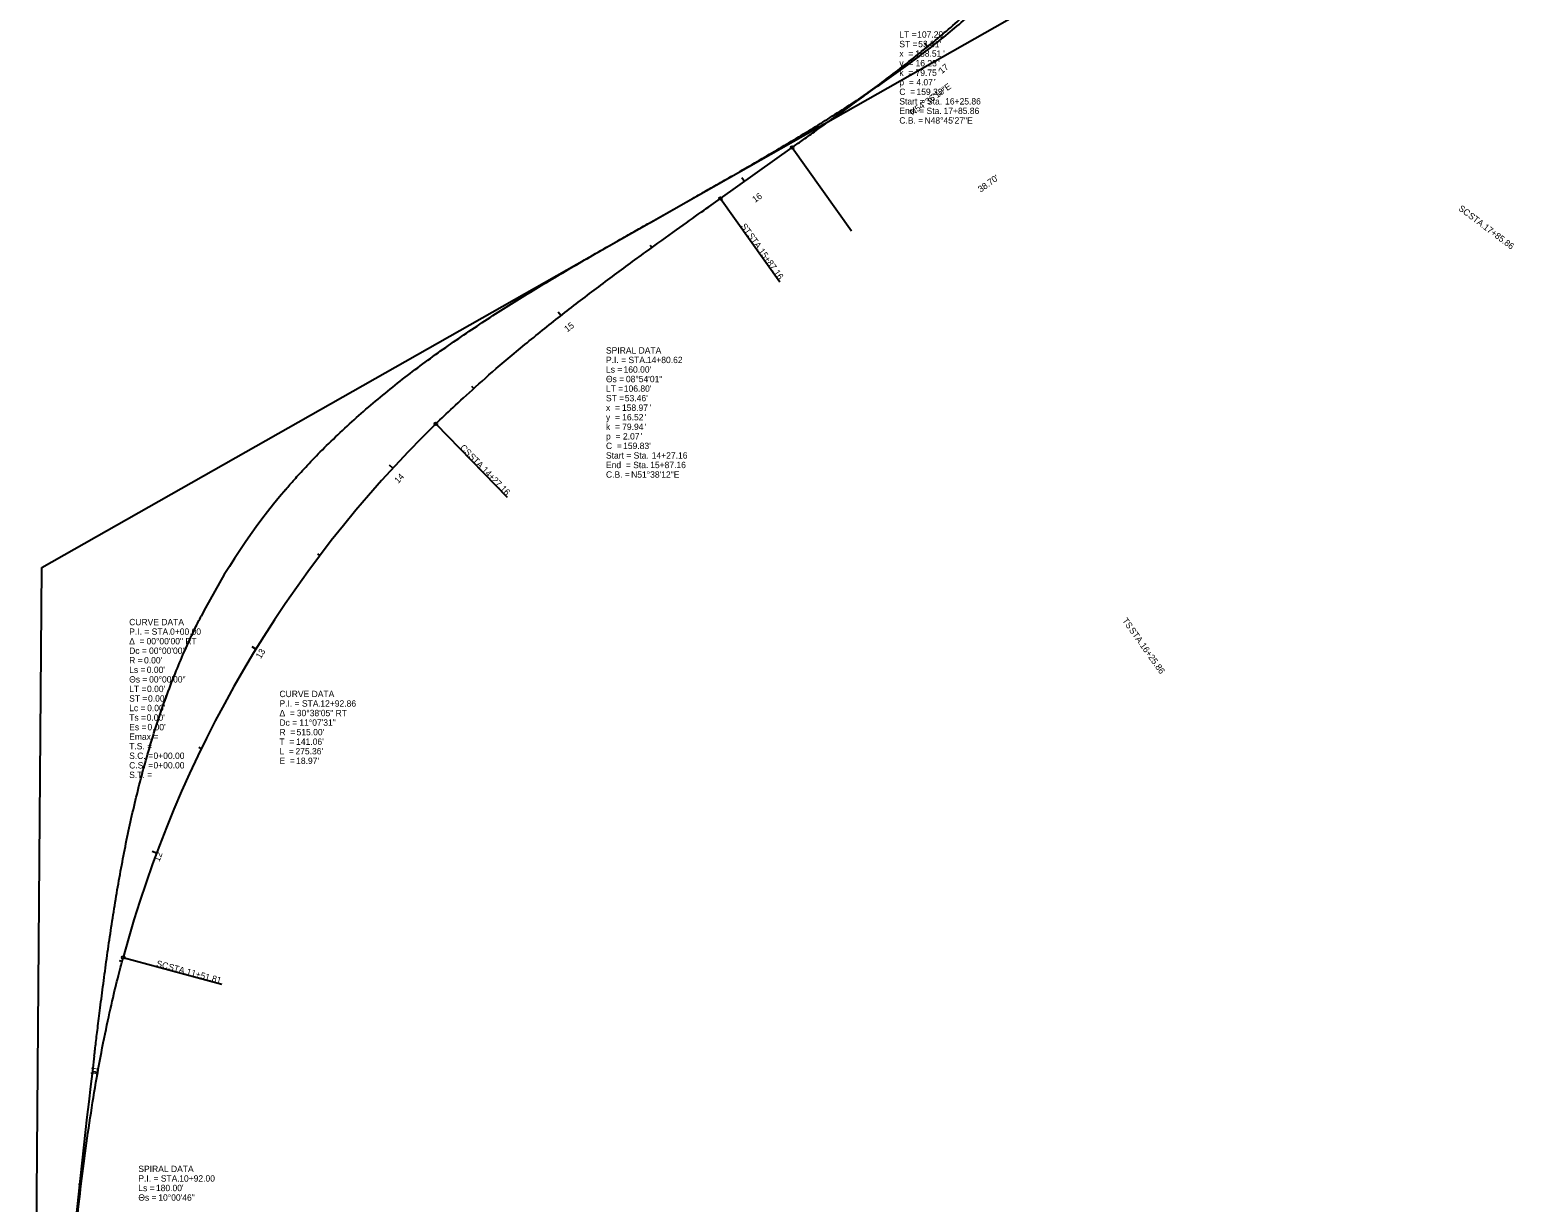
# Model space of a CAD drawing. Extents: x 1504629 to 1506299, y 325931 to 328016.
# Drawn here: x 1504639 to 1505293, y 326974 to 327489 of the extents above; entities that cross this region are included whole.
import ezdxf

# ---------------------------------------------------------------- set-up
doc = ezdxf.new("R2010")
doc.units = 0
for name, color, linetype in [('DV_X_Property_Line', 7, 'Continuous'), ('GE_X_Alignment', 7, 'Continuous'), ('GE_X_Alignment_100_Bearings', 7, 'Continuous'), ('GE_X_Alignment_100_Cardinal_Points', 7, 'Continuous'), ('GE_X_Alignment_100_Curve_Data', 7, 'Continuous'), ('GE_X_Alignment_100_Distances', 7, 'Continuous'), ('GE_X_Alignment_100_Stations', 7, 'Continuous'), ('SC_Scratch7', 7, 'Continuous'), ('SC_Scratch8', 7, 'Continuous')]:
    doc.layers.add(name, color=color, linetype=linetype)

msp = doc.modelspace()

# ---------------------------------------------------------------- linework, layer by layer
at = {"layer": 'DV_X_Property_Line'}
msp.add_line((1504943.35, 327415.15), (1504974.89, 327437.57), dxfattribs=at)
at = {"layer": 'GE_X_Alignment'}
msp.add_line((1504943.35, 327415.15), (1504974.89, 327437.57), dxfattribs=at)
msp.add_arc((1505177.7, 326947.36), 515, 134.2975, 164.93216, dxfattribs=at)
msp.add_arc((1505177.7, 326947.36), 515, 134.2975, 164.93216, dxfattribs=at)
for points in [[(1504974.89, 327437.57), (1504976.25, 327438.53), (1504978.97, 327440.47), (1504984.4, 327444.33), (1504991.18, 327449.17), (1504999.29, 327455.02), (1505007.36, 327460.93), (1505015.37, 327466.92), (1505023.31, 327473), (1505031.16, 327479.2), (1505038.91, 327485.52), (1505046.53, 327491.99), (1505054.01, 327498.63), (1505061.33, 327505.44), (1505068.47, 327512.44), (1505075.41, 327519.65), (1505082.12, 327527.07), (1505087.5, 327533.43), (1505091.66, 327538.64), (1505093.7, 327541.28), (1505094.7, 327542.61)], [(1504818.03, 327315.96), (1504820.42, 327318.28), (1504825.23, 327322.89), (1504835.03, 327331.94), (1504847.57, 327342.92), (1504862.98, 327355.67), (1504878.71, 327368.03), (1504894.67, 327380.08), (1504910.8, 327391.91), (1504924.34, 327401.63), (1504935.2, 327409.36), (1504940.63, 327413.22), (1504943.35, 327415.15)], [(1504818.03, 327315.96), (1504820.42, 327318.28), (1504825.23, 327322.89), (1504835.03, 327331.94), (1504847.57, 327342.92), (1504862.98, 327355.67), (1504878.71, 327368.03), (1504894.67, 327380.08), (1504910.8, 327391.91), (1504924.34, 327401.63), (1504935.2, 327409.36), (1504940.63, 327413.22), (1504943.35, 327415.15)], [(1504654.17, 326903.41), (1504654.43, 326906.4), (1504654.96, 326912.37), (1504656.03, 326924.33), (1504657.41, 326939.26), (1504659.18, 326957.18), (1504661.14, 326975.07), (1504663.35, 326992.93), (1504665.88, 327010.76), (1504668.77, 327028.52), (1504672.1, 327046.21), (1504675.29, 327060.87), (1504678.11, 327072.54), (1504679.62, 327078.34), (1504680.4, 327081.24)], [(1504654.17, 326903.41), (1504654.43, 326906.4), (1504654.96, 326912.37), (1504656.03, 326924.33), (1504657.41, 326939.26), (1504659.18, 326957.18), (1504661.14, 326975.07), (1504663.35, 326992.93), (1504665.88, 327010.76), (1504668.77, 327028.52), (1504672.1, 327046.21), (1504675.29, 327060.87), (1504678.11, 327072.54), (1504679.62, 327078.34), (1504680.4, 327081.24)]]:
    msp.add_open_spline(points, degree=3, dxfattribs=at)
at = {"layer": 'GE_X_Alignment_100_Cardinal_Points'}
for p, q in [((1504974.89, 327437.57), (1505000.96, 327400.89)), ((1504943.35, 327415.15), (1504969.42, 327378.47)), ((1504818.03, 327315.96), (1504849.46, 327283.75)), ((1504680.4, 327081.24), (1504723.86, 327069.54))]:
    msp.add_line(p, q, dxfattribs=at)
for centre in [(1504974.89, 327437.57), (1504943.35, 327415.15), (1504818.03, 327315.96), (1504680.4, 327081.24)]:
    msp.add_circle(centre, 0.6, dxfattribs=at)
at = {"layer": 'GE_X_Alignment_100_Stations'}
for p, q in [((1505034.36, 327481.82), (1505033.1, 327483.37)), ((1504994.54, 327451.6), (1504993.84, 327452.57)), ((1504953.81, 327422.59), (1504952.65, 327424.22)), ((1504913.11, 327393.54), (1504912.41, 327394.51)), ((1504873.09, 327363.58), (1504871.86, 327365.16)), ((1504834.71, 327331.55), (1504833.9, 327332.45)), ((1504799.1, 327296.48), (1504797.63, 327297.84)), ((1504767.04, 327258.14), (1504766.08, 327258.86)), ((1504738.85, 327216.87), (1504737.14, 327217.91)), ((1504714.79, 327173.06), (1504713.71, 327173.58)), ((1504695.09, 327127.12), (1504693.22, 327127.82)), ((1504679.94, 327079.49), (1504678.78, 327079.8)), ((1504669.23, 327030.67), (1504667.26, 327031.02)), ((1504661.92, 326981.21), (1504660.72, 326981.36))]:
    msp.add_line(p, q, dxfattribs=at)
at = {"layer": 'SC_Scratch7'}
for p, q in [((1504644.71, 327252.82), (1505148.27, 327538.35)), ((1504639.3, 326603.71), (1504644.71, 327252.82))]:
    msp.add_line(p, q, dxfattribs=at)
at = {"layer": 'SC_Scratch8'}
msp.add_line((1504912.45, 327404.63), (1504931.21, 327415.27), dxfattribs=at)
for centre, radius, start, end in [((1504969.97, 327101.26), 286.48, 139.55359, 152.98901), ((1508458.87, 326571.85), 3819.7, 172.98893, 179.52215)]:
    msp.add_arc(centre, radius, start, end, dxfattribs=at)
for points in [[(1504931.21, 327415.27), (1504932.66, 327416.09), (1504935.56, 327417.74), (1504941.36, 327421.03), (1504948.6, 327425.15), (1504957.27, 327430.13), (1504965.91, 327435.17), (1504974.51, 327440.26), (1504983.07, 327445.44), (1504991.56, 327450.72), (1504999.98, 327456.11), (1505008.32, 327461.63), (1505016.56, 327467.3), (1505024.7, 327473.12), (1505032.71, 327479.11), (1505040.57, 327485.28), (1505048.29, 327491.64), (1505055.83, 327498.21), (1505063.18, 327505), (1505070.31, 327512), (1505077.22, 327519.24), (1505082.76, 327525.46), (1505087.06, 327530.56), (1505089.16, 327533.15), (1505090.2, 327534.45)], [(1504751.96, 327287.11), (1504753.16, 327288.52), (1504755.59, 327291.32), (1504760.55, 327296.81), (1504766.94, 327303.51), (1504774.89, 327311.28), (1504783.08, 327318.79), (1504791.49, 327326.05), (1504800.11, 327333.07), (1504808.9, 327339.87), (1504817.85, 327346.46), (1504826.94, 327352.85), (1504836.15, 327359.06), (1504845.47, 327365.11), (1504854.88, 327371.02), (1504864.36, 327376.81), (1504873.91, 327382.5), (1504883.5, 327388.11), (1504893.13, 327393.65), (1504901.17, 327398.23), (1504907.62, 327401.89), (1504910.84, 327403.72), (1504912.45, 327404.63)], [(1504667.73, 327038.09), (1504667.95, 327039.92), (1504668.41, 327043.6), (1504669.31, 327050.95), (1504670.46, 327060.14), (1504671.89, 327071.16), (1504673.39, 327082.17), (1504674.98, 327093.16), (1504676.7, 327104.14), (1504678.55, 327115.1), (1504680.57, 327126.03), (1504682.77, 327136.92), (1504685.19, 327147.76), (1504687.84, 327158.55), (1504690.75, 327169.28), (1504693.93, 327179.92), (1504697.41, 327190.48), (1504701.21, 327200.92), (1504705.34, 327211.24), (1504709.07, 327219.71), (1504712.25, 327226.4), (1504713.9, 327229.72), (1504714.74, 327231.37)]]:
    msp.add_open_spline(points, degree=3, dxfattribs=at)

# ---------------------------------------------------------------- texts
at = {"layer": 'GE_X_Alignment_100_Bearings'}
msp.add_text('N54°36\'10"E', height=2.8, rotation=35.39718, dxfattribs=at).set_placement((1505027.8, 327451.48))
at = {"layer": 'GE_X_Alignment_100_Cardinal_Points'}
for s, rotation, p in [('SC', 322.94701, (1505267.76, 327410.24)), ('ST', 305.39718, (1504952.09, 327402.92)), (' STA. ', 322.94701, (1505271.24, 327407.61)), ('17+85.86', 322.94701, (1505278.68, 327401.99)), (' STA. ', 305.39718, (1504954.47, 327399.57)), ('15+87.16', 305.39718, (1504959.87, 327391.97)), ('CS', 314.2975, (1504828.47, 327305.31)), (' STA. ', 314.2975, (1504831.52, 327302.19)), ('14+27.16', 314.2975, (1504838.03, 327295.52)), ('TS', 305.39718, (1505119.93, 327229.44)), (' STA. ', 305.39718, (1505122.32, 327226.09)), ('16+25.86', 305.39718, (1505127.72, 327218.49)), ('SC', 344.93216, (1504694.85, 327077.39)), (' STA. ', 344.93216, (1504699.05, 327076.26)), ('11+51.81', 344.93216, (1504708.06, 327073.83))]:
    msp.add_text(s, height=2.8, rotation=rotation, dxfattribs=at).set_placement(p)
at = {"layer": 'GE_X_Alignment_100_Curve_Data'}
for s, p in [('LT = ', (1505022, 327485.86)), ("107.20'", (1505029.85, 327485.86)), ('ST = ', (1505022, 327481.66)), ("53.81'", (1505030.3, 327481.66)), ('y  = ', (1505022, 327473.26)), ('x  = ', (1505022, 327477.46)), ('158.51', (1505029.03, 327477.46)), ('16.23', (1505029.13, 327473.26)), ("'", (1505039.15, 327473.26)), ("'", (1505041.28, 327477.46)), ('k  = ', (1505022, 327469.06)), ('79.75', (1505029.13, 327469.06)), ("'", (1505039.15, 327469.06)), ('C  = ', (1505022, 327460.66)), ('p  = ', (1505022, 327464.86)), ('4.07', (1505029.48, 327464.86)), ("159.33'", (1505029.55, 327460.66)), ("'", (1505037.26, 327464.86)), ('Start = Sta. ', (1505022, 327456.46)), ('16+25.86', (1505042.15, 327456.46)), ('C.B. = ', (1505022, 327448.06)), ('End  = Sta. ', (1505022, 327452.26)), ('N48°45\'27"E', (1505033.07, 327448.06)), ('17+85.86', (1505041.46, 327452.26)), ('SPIRAL DATA', (1504892.9, 327346.91)), ('P.I. = STA. ', (1504892.9, 327342.71)), ('14+80.62', (1504910.89, 327342.71)), ('Ls = ', (1504892.9, 327338.51)), ("160.00'", (1504900.64, 327338.51)), ('Θs = ', (1504892.9, 327334.31)), ('LT = ', (1504892.9, 327330.11)), ("106.80'", (1504900.75, 327330.11)), ('08°54\'01"', (1504901.68, 327334.31)), ('ST = ', (1504892.9, 327325.91)), ("53.46'", (1504901.2, 327325.91)), ('y  = ', (1504892.9, 327317.51)), ('x  = ', (1504892.9, 327321.71)), ('158.97', (1504899.93, 327321.71)), ('16.52', (1504900.03, 327317.51)), ("'", (1504910.05, 327317.51)), ("'", (1504912.18, 327321.71)), ('k  = ', (1504892.9, 327313.31)), ('79.94', (1504900.03, 327313.31)), ('2.07', (1504900.38, 327309.11)), ("'", (1504908.16, 327309.11)), ("'", (1504910.05, 327313.31)), ('C  = ', (1504892.9, 327304.91)), ('p  = ', (1504892.9, 327309.11)), ("159.83'", (1504900.45, 327304.91)), ('Start = Sta. ', (1504892.9, 327300.71)), ('End  = Sta. ', (1504892.9, 327296.51)), ('15+87.16', (1504912.36, 327296.51)), ('14+27.16', (1504913.05, 327300.71)), ('C.B. = ', (1504892.9, 327292.31)), ('N51°38\'12"E', (1504903.97, 327292.31)), ('CURVE DATA', (1504683.08, 327227.41)), ('Δ  = ', (1504683.08, 327219.01)), ('P.I. = STA. ', (1504683.08, 327223.21)), ('00°00\'00" RT', (1504690.72, 327219.01)), ('0+00.00', (1504701.07, 327223.21)), ('Dc = ', (1504683.08, 327214.81)), ('00°00\'00"', (1504691.82, 327214.81)), ('R = ', (1504683.08, 327210.61)), ('Ls = ', (1504683.08, 327206.41)), ("0.00'", (1504689.62, 327210.61)), ("0.00'", (1504690.82, 327206.41)), ('Θs = ', (1504683.08, 327202.21)), ('LT = ', (1504683.08, 327198.01)), ("0.00'", (1504690.93, 327198.01)), ('00°00\'00"', (1504691.86, 327202.21)), ('ST = ', (1504683.08, 327193.81)), ("0.00'", (1504691.38, 327193.81)), ('CURVE DATA', (1504749.22, 327195.8)), ('P.I. = STA. ', (1504749.22, 327191.6)), ('12+92.86', (1504767.21, 327191.6)), ('Ts = ', (1504683.08, 327185.41)), ('Lc = ', (1504683.08, 327189.61)), ("0.00'", (1504690.76, 327185.41)), ("0.00'", (1504690.99, 327189.61)), ('Δ  = ', (1504749.22, 327187.4)), ('30°38\'05" RT', (1504756.86, 327187.4)), ('Es = ', (1504683.08, 327181.21)), ("0.00'", (1504691.13, 327181.21)), ('Dc = ', (1504749.22, 327183.2)), ('R  = ', (1504749.22, 327179)), ("515.00'", (1504756.75, 327179)), ('11°07\'31"', (1504757.96, 327183.2)), ('T.S. = ', (1504683.08, 327172.81)), ('Emax = ', (1504683.08, 327177.01)), ('T  = ', (1504749.22, 327174.8)), ("141.06'", (1504756.54, 327174.8)), ('S.C. = ', (1504683.08, 327168.61)), ('0+00.00', (1504693.78, 327168.61)), ('L  = ', (1504749.22, 327170.6)), ('E  = ', (1504749.22, 327166.4)), ("275.36'", (1504756.25, 327170.6)), ("18.97'", (1504756.56, 327166.4)), ('S.T. = ', (1504683.08, 327160.21)), ('C.S. = ', (1504683.08, 327164.41)), ('0+00.00', (1504693.78, 327164.41)), ('SPIRAL DATA', (1504687.11, 326986.89)), ('P.I. = STA. ', (1504687.11, 326982.69)), ('10+92.00', (1504705.1, 326982.69)), ('Ls = ', (1504687.11, 326978.49)), ("180.00'", (1504694.86, 326978.49)), ('Θs = ', (1504687.11, 326974.29)), ('10°00\'46"', (1504695.9, 326974.29))]:
    msp.add_text(s, height=2.8, dxfattribs=at).set_placement(p)
at = {"layer": 'GE_X_Alignment_100_Distances'}
msp.add_text("38.70'", height=2.8, rotation=35.39718, dxfattribs=at).set_placement((1505057.82, 327417.68))
at = {"layer": 'GE_X_Alignment_100_Stations'}
for s, rotation, p in [('17', 39.16512, (1505040.74, 327469.82)), ('16', 35.39718, (1504958.5, 327413.15)), ('15', 38.03868, (1504875.88, 327356.19)), ('14', 47.31971, (1504801.48, 327289.56)), ('13', 58.4451, (1504740.97, 327212.44)), ('12', 69.5705, (1504696.38, 327123.18)), ('11', 79.86644, (1504668.64, 327029.04))]:
    msp.add_text(s, height=2.8, rotation=rotation, dxfattribs=at).set_placement(p)

doc.saveas('drawing.dxf')
